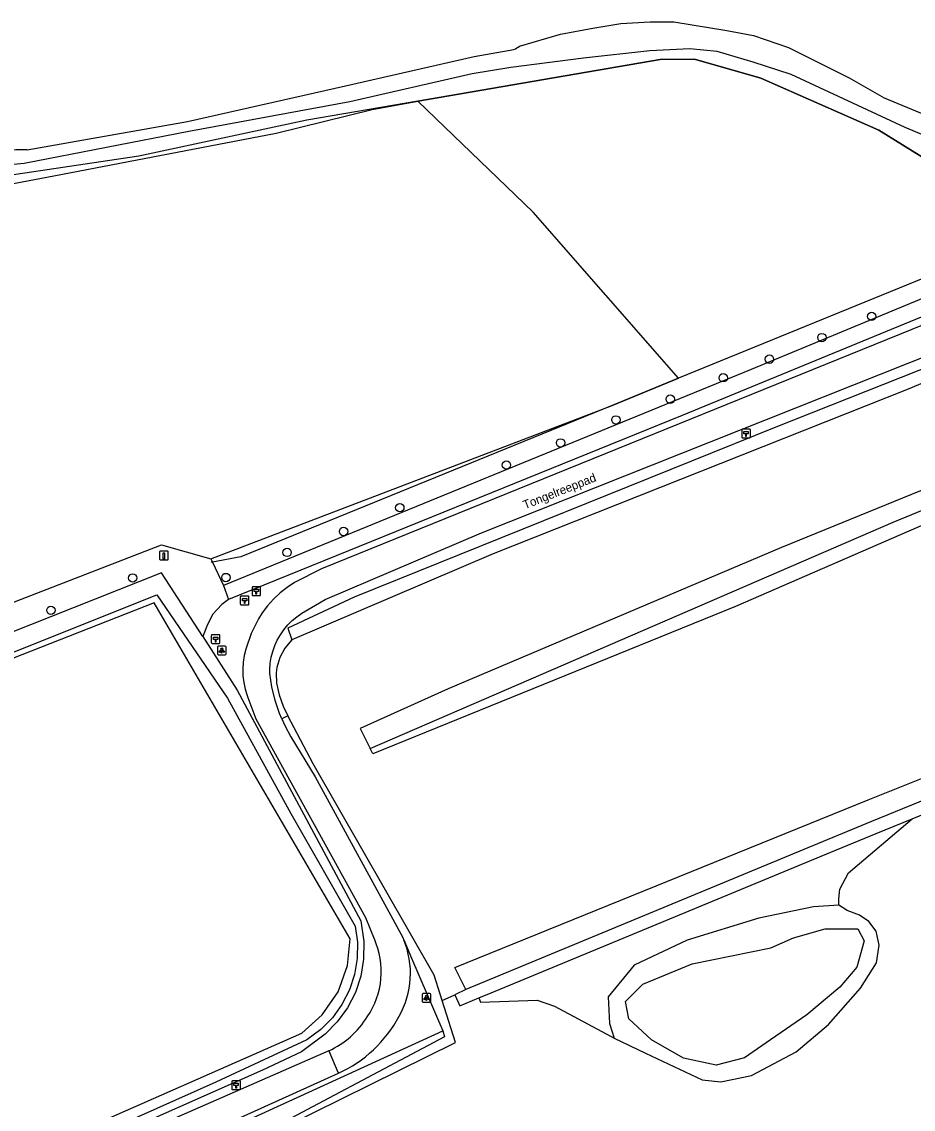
# Model space of a CAD drawing. Extents: x 160203 to 161526, y 379529 to 381797.
# Drawn here: x 161344.7 to 161448.3, y 381317.5 to 381443.9 of the extents above; entities that cross this region are included whole.
import ezdxf

# ---------------------------------------------------------------- set-up
doc = ezdxf.new("R2010")
doc.units = 0
for name, color, linetype in [('IMGEO_Boom', 7, 'Continuous'), ('IMGEO_Gemengd_bos', 7, 'Continuous'), ('IMGEO_Grasland_agrarisch', 7, 'Continuous'), ('IMGEO_Grasland_overig', 7, 'Continuous'), ('IMGEO_Hectometerpaal', 7, 'Continuous'), ('IMGEO_Hek', 7, 'Continuous'), ('IMGEO_Lichtpunt', 7, 'Continuous'), ('IMGEO_Loofbos', 7, 'Continuous'), ('IMGEO_Meer_plas_ven_vijver', 7, 'Continuous'), ('IMGEO_Openbare_ruimte_label', 7, 'Continuous'), ('IMGEO_Paal', 7, 'Continuous'), ('IMGEO_Rijbaan_lokaal_gesloten', 7, 'Continuous'), ('IMGEO_Rijbaan_lokaal_halfverhard', 7, 'Continuous'), ('IMGEO_Voetpad_onverhard', 7, 'Continuous'), ('IMGEO_Waterloop', 7, 'Continuous')]:
    doc.layers.add(name, color=color, linetype=linetype)

msp = doc.modelspace()

# ---------------------------------------------------------------- linework, layer by layer
at = {"layer": 'IMGEO_Boom'}
for centre in [(161443.45, 381409.65), (161437.67, 381407.18), (161431.57, 381404.67), (161426.21, 381402.51), (161420.05, 381400.02), (161413.74, 381397.61), (161407.31, 381394.94), (161401.01, 381392.37), (161388.62, 381387.41), (161382.09, 381384.64), (161375.52, 381382.21), (161368.42, 381379.29), (161357.58, 381379.24), (161348.08, 381375.48)]:
    msp.add_circle(centre, 0.489, dxfattribs=at)
at = {"layer": 'IMGEO_Gemengd_bos'}
for points in [[(161421.01, 381402.45), (161404.11, 381421.75), (161390.71, 381434.67)], [(161461.38, 381418.93), (161421.01, 381402.45)]]:
    msp.add_lwpolyline(points, dxfattribs=at)
at = {"layer": 'IMGEO_Grasland_agrarisch'}
for points in [[(161366.65, 381381.48), (161413.3, 381399.3), (161421.01, 381402.45)], [(161300.42, 381292.52), (161377.22, 381326.32), (161379.59, 381328.48), (161381.46, 381331.14), (161382.56, 381334.21), (161382.85, 381337.29), (161360.06, 381376.34), (161223.13, 381322.55)], [(161376.08, 381372.04), (161375.28, 381371.1), (161374.7, 381370.01), (161374.35, 381368.83), (161374.27, 381368.21), (161374.3, 381367.02), (161374.62, 381365.65), (161375.08, 381364.32), (161375.6, 381363.2)], [(161413.54, 381325.76), (161417.16, 381324.01), (161423.76, 381320.89), (161425.94, 381320.66), (161429.49, 381321.4), (161434.69, 381324.15), (161438.42, 381327.35), (161442.14, 381331.58), (161444.03, 381334.51), (161444.32, 381336.57), (161443.97, 381338.17), (161443.11, 381339.31), (161442.03, 381340.05), (161440.6, 381340.57), (161439.62, 381341.2)], [(161393.54, 381330.12), (161395.02, 381330.77)]]:
    msp.add_lwpolyline(points, dxfattribs=at)
at = {"layer": 'IMGEO_Grasland_overig'}
for points in [[(161477.98, 381397.82), (161427.64, 381375.92), (161385.47, 381358.79), (161385.17, 381359.4)], [(161375.6, 381363.2), (161374.93, 381362.86)], [(161393.54, 381330.12), (161392.6, 381333.07), (161378.56, 381357.65), (161375.6, 381363.2)], [(161439.62, 381341.2), (161439.62, 381341.94), (161439.74, 381343.08), (161440.77, 381344.97), (161448.15, 381351.25)], [(161439.62, 381341.2), (161436.69, 381341.02), (161430.33, 381339.69), (161422.02, 381337.13), (161415.85, 381334.22), (161412.82, 381330.54), (161413, 381327.46), (161413.54, 381325.76)], [(161389.08, 381337.19), (161390, 381335.06), (161393.64, 381326.61)], [(161371.98, 381313.8), (161395.1, 381325.23), (161393.54, 381330.12)], [(161397.82, 381330.42), (161397.99, 381329.92), (161404.58, 381330.15), (161406.58, 381329.47), (161413.17, 381325.94), (161413.54, 381325.76)]]:
    msp.add_lwpolyline(points, dxfattribs=at)
at = {"layer": 'IMGEO_Hectometerpaal'}
for p, q in [((161428.36, 381396.46), (161428.36, 381395.62)), ((161428.36, 381396.46), (161428.36, 381395.62)), ((161429.27, 381396.54), (161428.43, 381396.54)), ((161429.27, 381396.54), (161428.43, 381396.54)), ((161429.36, 381395.63), (161429.36, 381396.47)), ((161429.36, 381395.63), (161429.36, 381396.47)), ((161428.44, 381395.54), (161429.28, 381395.54)), ((161428.44, 381395.54), (161429.28, 381395.54)), ((161371.45, 381378.12), (161371.45, 381377.28)), ((161371.45, 381378.12), (161371.45, 381377.28)), ((161372.36, 381378.2), (161371.52, 381378.2)), ((161372.36, 381378.2), (161371.52, 381378.2)), ((161372.45, 381377.29), (161372.45, 381378.13)), ((161372.45, 381377.29), (161372.45, 381378.13)), ((161370.09, 381377.03), (161370.09, 381376.19)), ((161370.09, 381377.03), (161370.09, 381376.19)), ((161371.01, 381377.12), (161370.16, 381377.12)), ((161371.01, 381377.12), (161370.16, 381377.12)), ((161370.17, 381376.12), (161371.02, 381376.12)), ((161370.17, 381376.12), (161371.02, 381376.12)), ((161371.09, 381376.2), (161371.09, 381377.04)), ((161371.09, 381376.2), (161371.09, 381377.04)), ((161371.53, 381377.2), (161372.37, 381377.2)), ((161371.53, 381377.2), (161372.37, 381377.2)), ((161366.72, 381372.56), (161366.72, 381371.71)), ((161366.72, 381372.56), (161366.72, 381371.71)), ((161367.64, 381372.64), (161366.8, 381372.64)), ((161367.64, 381372.64), (161366.8, 381372.64)), ((161367.72, 381371.72), (161367.72, 381372.57)), ((161367.72, 381371.72), (161367.72, 381372.57)), ((161366.81, 381371.64), (161367.65, 381371.64)), ((161366.81, 381371.64), (161367.65, 381371.64)), ((161369.11, 381320.7), (161369.11, 381319.86)), ((161369.11, 381320.7), (161369.11, 381319.86)), ((161370.02, 381320.78), (161369.18, 381320.78)), ((161370.02, 381320.78), (161369.18, 381320.78)), ((161370.1, 381319.87), (161370.1, 381320.71)), ((161370.1, 381319.87), (161370.1, 381320.71)), ((161369.19, 381319.78), (161370.03, 381319.78)), ((161369.19, 381319.78), (161370.03, 381319.78))]:
    msp.add_line(p, q, dxfattribs=at)
for points in [[(161428.88, 381395.69), (161428.82, 381395.69), (161428.82, 381395.99), (161428.6, 381395.99), (161428.6, 381396.26), (161429.1, 381396.26), (161429.1, 381395.99), (161428.88, 381395.99), (161428.88, 381395.69)], [(161371.97, 381377.35), (161371.91, 381377.35), (161371.91, 381377.65), (161371.69, 381377.65), (161371.69, 381377.92), (161372.19, 381377.92), (161372.19, 381377.65), (161371.97, 381377.65), (161371.97, 381377.35)], [(161370.62, 381376.26), (161370.56, 381376.26), (161370.56, 381376.57), (161370.34, 381376.57), (161370.34, 381376.84), (161370.84, 381376.84), (161370.84, 381376.57), (161370.62, 381376.57), (161370.62, 381376.26)], [(161367.25, 381371.78), (161367.19, 381371.78), (161367.19, 381372.09), (161366.97, 381372.09), (161366.97, 381372.36), (161367.47, 381372.36), (161367.47, 381372.09), (161367.25, 381372.09), (161367.25, 381371.78)], [(161369.63, 381319.93), (161369.57, 381319.93), (161369.57, 381320.23), (161369.35, 381320.23), (161369.35, 381320.5), (161369.85, 381320.5), (161369.85, 381320.23), (161369.63, 381320.23), (161369.63, 381319.93)]]:
    msp.add_lwpolyline(points, dxfattribs=at)
for centre, start, end in [((161428.43, 381396.46), 92.4484, 184.2845), ((161428.43, 381396.46), 92.4484, 184.2845), ((161429.28, 381396.46), 2.4484, 94.2845), ((161429.28, 381396.46), 2.4484, 94.2845), ((161428.43, 381395.62), 182.4484, 274.2845), ((161428.43, 381395.62), 182.4484, 274.2845), ((161429.28, 381395.62), 272.4484, 4.2845), ((161429.28, 381395.62), 272.4484, 4.2845), ((161371.53, 381378.12), 92.4484, 184.2845), ((161371.53, 381378.12), 92.4484, 184.2845), ((161371.53, 381377.28), 182.4484, 274.2845), ((161371.53, 381377.28), 182.4484, 274.2845), ((161372.37, 381378.12), 2.4484, 94.2845), ((161372.37, 381378.12), 2.4484, 94.2845), ((161372.37, 381377.28), 272.4484, 4.2845), ((161372.37, 381377.28), 272.4484, 4.2845), ((161370.17, 381377.04), 92.4484, 184.2845), ((161370.17, 381377.04), 92.4484, 184.2845), ((161370.17, 381376.2), 182.4484, 274.2845), ((161370.17, 381376.2), 182.4484, 274.2845), ((161371.01, 381377.04), 2.4484, 94.2845), ((161371.01, 381377.04), 2.4484, 94.2845), ((161371.01, 381376.2), 272.4484, 4.2845), ((161371.01, 381376.2), 272.4484, 4.2845), ((161366.8, 381372.56), 92.4484, 184.2845), ((161366.8, 381372.56), 92.4484, 184.2845), ((161367.65, 381372.56), 2.4484, 94.2845), ((161367.65, 381372.56), 2.4484, 94.2845), ((161366.8, 381371.72), 182.4484, 274.2845), ((161366.8, 381371.72), 182.4484, 274.2845), ((161367.65, 381371.72), 272.4484, 4.2845), ((161367.65, 381371.72), 272.4484, 4.2845), ((161369.18, 381320.7), 92.4484, 184.2845), ((161369.18, 381320.7), 92.4484, 184.2845), ((161370.03, 381320.7), 2.4484, 94.2845), ((161370.03, 381320.7), 2.4484, 94.2845), ((161369.18, 381319.86), 182.4484, 274.2845), ((161369.18, 381319.86), 182.4484, 274.2845), ((161370.03, 381319.86), 272.4484, 4.2845), ((161370.03, 381319.86), 272.4484, 4.2845)]:
    msp.add_arc(centre, 0.0779, start, end, dxfattribs=at)
at = {"layer": 'IMGEO_Hek'}
for points in [[(161461.38, 381418.93), (161460.88, 381420.19), (161457.83, 381422.88), (161444.27, 381431.28), (161430.57, 381437.32), (161422.85, 381439.54), (161418.88, 381439.5), (161390.71, 381434.67)], [(161390.71, 381434.67), (161377.8, 381432.45), (161358.29, 381428.28), (161335.14, 381424.83), (161323.67, 381420.86), (161316.26, 381417.47), (161305.01, 381413.91), (161280.48, 381402.76)], [(161461.38, 381418.93), (161421.01, 381402.45)], [(161421.01, 381402.45), (161413.3, 381399.3)], [(161413.3, 381399.3), (161370.15, 381381.69), (161366.84, 381381.09)], [(161366.65, 381381.48), (161366.84, 381381.09)], [(161366.84, 381381.09), (161366.69, 381381.07)], [(161366.84, 381381.09), (161368.12, 381378.37)], [(161300.42, 381292.52), (161377.22, 381326.32), (161379.59, 381328.48), (161381.46, 381331.14), (161382.56, 381334.21), (161382.85, 381337.29), (161360.06, 381376.34), (161223.13, 381322.55)]]:
    msp.add_lwpolyline(points, dxfattribs=at)
at = {"layer": 'IMGEO_Lichtpunt'}
for p, q in [((161367.44, 381371.22), (161367.44, 381370.41)), ((161367.44, 381371.22), (161367.44, 381370.41)), ((161368.34, 381371.31), (161367.53, 381371.31)), ((161368.34, 381371.31), (161367.53, 381371.31)), ((161368.43, 381370.41), (161368.43, 381371.22)), ((161368.43, 381370.41), (161368.43, 381371.22)), ((161367.53, 381370.32), (161368.34, 381370.32)), ((161367.53, 381370.32), (161368.34, 381370.32)), ((161391.22, 381330.83), (161391.22, 381330.03)), ((161391.22, 381330.83), (161391.22, 381330.03)), ((161392.12, 381330.93), (161391.31, 381330.93)), ((161392.12, 381330.93), (161391.31, 381330.93)), ((161392.22, 381330.03), (161392.22, 381330.83)), ((161392.22, 381330.03), (161392.22, 381330.83)), ((161391.31, 381329.93), (161392.12, 381329.93)), ((161391.31, 381329.93), (161392.12, 381329.93))]:
    msp.add_line(p, q, dxfattribs=at)
for points in [[(161367.81, 381370.88), (161367.85, 381370.86), (161367.66, 381370.59), (161367.62, 381370.62), (161367.81, 381370.88)], [(161367.91, 381370.84), (161367.96, 381370.84), (161367.96, 381370.51), (161367.91, 381370.51), (161367.91, 381370.84)], [(161368.02, 381370.86), (161368.06, 381370.88), (161368.25, 381370.62), (161368.21, 381370.59), (161368.02, 381370.86)], [(161391.59, 381330.5), (161391.63, 381330.47), (161391.45, 381330.21), (161391.41, 381330.23), (161391.59, 381330.5)], [(161391.81, 381330.47), (161391.84, 381330.5), (161392.03, 381330.23), (161391.99, 381330.21), (161391.81, 381330.47)], [(161391.7, 381330.45), (161391.74, 381330.45), (161391.74, 381330.13), (161391.7, 381330.13), (161391.7, 381330.45)]]:
    msp.add_lwpolyline(points, dxfattribs=at)
for centre in [(161367.94, 381371.02), (161391.72, 381330.63)]:
    msp.add_circle(centre, 0.0994, dxfattribs=at)
for centre, start, end in [((161367.53, 381371.22), 90, 180), ((161367.53, 381371.22), 90, 180), ((161368.34, 381371.22), 0, 90), ((161368.34, 381371.22), 0, 90), ((161367.53, 381370.41), 180, 270), ((161367.53, 381370.41), 180, 270), ((161368.34, 381370.41), 270, 0), ((161368.34, 381370.41), 270, 360), ((161391.31, 381330.83), 90, 180), ((161391.31, 381330.83), 90, 180), ((161392.12, 381330.83), 0, 90), ((161392.12, 381330.83), 0, 90), ((161391.31, 381330.03), 180, 270), ((161391.31, 381330.03), 180, 270), ((161392.12, 381330.03), 270, 0), ((161392.12, 381330.03), 270, 360)]:
    msp.add_arc(centre, 0.0946, start, end, dxfattribs=at)
at = {"layer": 'IMGEO_Loofbos'}
for points in [[(161448.15, 381351.25), (161475.37, 381362.37), (161489.26, 381368.04), (161488.64, 381369.4)], [(161397.82, 381330.42), (161399.23, 381331.01), (161404.18, 381333.06), (161438.72, 381347.37), (161443.96, 381349.54), (161448.15, 381351.25)], [(161396.31, 381331.42), (161395.02, 381330.77)], [(161395.02, 381330.77), (161395.6, 381329.51), (161397.82, 381330.42)]]:
    msp.add_lwpolyline(points, dxfattribs=at)
at = {"layer": 'IMGEO_Meer_plas_ven_vijver'}
msp.add_lwpolyline([(161438.04, 381338.47), (161441.85, 381338.47), (161442.59, 381337.05), (161441.72, 381334.01), (161439.74, 381331.67), (161435.93, 381328.45), (161431.7, 381325.56), (161428.66, 381323.48), (161425.4, 381322.61), (161421.59, 381323.44), (161417.87, 381325.56), (161415.25, 381327.99), (161414.83, 381330.02), (161416.86, 381332.04), (161422.6, 381334.38), (161431.72, 381336.24), (161434.36, 381337.42), (161438.04, 381338.47)], dxfattribs=at)
at = {"layer": 'IMGEO_Paal'}
for p, q in [((161361.63, 381382.35), (161360.78, 381382.35)), ((161361.63, 381382.35), (161360.78, 381382.35)), ((161361.71, 381381.44), (161361.71, 381382.28)), ((161361.71, 381381.44), (161361.71, 381382.28)), ((161360.71, 381382.27), (161360.71, 381381.43)), ((161360.71, 381382.27), (161360.71, 381381.43)), ((161360.79, 381381.35), (161361.64, 381381.35)), ((161360.79, 381381.35), (161361.64, 381381.35))]:
    msp.add_line(p, q, dxfattribs=at)
msp.add_lwpolyline([(161361.13, 381382.17), (161361.29, 381382.17), (161361.29, 381381.43), (161361.13, 381381.43), (161361.13, 381382.17)], dxfattribs=at)
for centre, start, end in [((161360.79, 381382.28), 92.4484, 184.2845), ((161360.79, 381382.28), 92.4484, 184.2845), ((161361.63, 381382.28), 2.4484, 94.2845), ((161361.63, 381382.28), 2.4484, 94.2845), ((161360.79, 381381.43), 182.4484, 274.2845), ((161360.79, 381381.43), 182.4484, 274.2845), ((161361.63, 381381.43), 272.4484, 4.2845), ((161361.63, 381381.43), 272.4484, 4.2845)]:
    msp.add_arc(centre, 0.0779, start, end, dxfattribs=at)
at = {"layer": 'IMGEO_Rijbaan_lokaal_gesloten'}
for points in [[(161469.38, 381416.15), (161468.35, 381416.31), (161468.18, 381416.24), (161379.51, 381380.32), (161376.4, 381378.7), (161375.53, 381378.14), (161374.71, 381377.5), (161373.95, 381376.79), (161373.26, 381376.02), (161372.64, 381375.18), (161372.21, 381374.5), (161371.35, 381372.78), (161370.73, 381370.97), (161370.54, 381370.21), (161370.42, 381369.44), (161370.37, 381368.65), (161370.39, 381367.87), (161370.49, 381367.09), (161370.65, 381366.33), (161370.88, 381365.58), (161370.96, 381365.35), (161371.9, 381362.86), (161384.63, 381339.79), (161385.66, 381337.28)], [(161374.93, 381362.86), (161374.65, 381363.49), (161374.14, 381365.01), (161373.76, 381366.57), (161373.53, 381368.15), (161373.52, 381368.6), (161373.57, 381369.32), (161373.69, 381370.02), (161373.86, 381370.71), (161374.1, 381371.38), (161374.39, 381372.03), (161374.74, 381372.65), (161375.15, 381373.23), (161375.6, 381373.78), (161376.11, 381374.28), (161376.65, 381374.74), (161377.24, 381375.15), (161379.93, 381376.75), (161398.12, 381384.47), (161467.77, 381412.19), (161469.08, 381412.98), (161470.21, 381414.22), (161470.56, 381414.35)], [(161374.93, 381362.86), (161375.3, 381362.02), (161375.97, 381360.78), (161378.77, 381356.14), (161388.96, 381337.45), (161389.02, 381337.32), (161389.08, 381337.19)], [(161380.36, 381324.29), (161300.01, 381289.1), (161268.1, 381275.47), (161255.77, 381270.11)], [(161380.36, 381324.29), (161381.43, 381321.81), (161381.5, 381321.67)], [(161108.29, 381192.8), (161114.38, 381197.57), (161123.38, 381204.59), (161125.79, 381205.94), (161175.21, 381228.65), (161209.02, 381245.57), (161218.78, 381250), (161257.16, 381267.43), (161261.42, 381269.36), (161301.19, 381286.35), (161354.19, 381309.33), (161381.5, 381321.67)]]:
    msp.add_lwpolyline(points, dxfattribs=at)
for centre, radius, start, end in [((161377.16, 381333.49), 9.31, 325.6381, 24.0278), ((161379.8, 381333.29), 10.06, 330.247, 22.7745), ((161376.22, 381333.51), 10.11, 294.177, 328.5272), ((161375.34, 381335.25), 14.91, 294.3759, 332.2212)]:
    msp.add_arc(centre, radius, start, end, dxfattribs=at)
at = {"layer": 'IMGEO_Rijbaan_lokaal_halfverhard'}
for points in [[(161267.77, 381346.99), (161360.92, 381383.1), (161366.65, 381381.48)], [(161366.65, 381381.48), (161366.84, 381381.09), (161368.12, 381378.37)], [(161365.72, 381372.42), (161360.95, 381379.85), (161271.8, 381344.48)], [(161368.12, 381378.37), (161368.71, 381376.75)], [(161368.71, 381376.75), (161367.93, 381376.17), (161366.87, 381374.98), (161366.2, 381373.65), (161365.72, 381372.42)]]:
    msp.add_lwpolyline(points, dxfattribs=at)
at = {"layer": 'IMGEO_Voetpad_onverhard'}
for points in [[(161458.71, 381424.79), (161457.27, 381425.64), (161457.1, 381427.27), (161452.08, 381429.64), (161447.34, 381431.6), (161434.1, 381437.78), (161429.69, 381439.19), (161425.48, 381440.42), (161422.31, 381440.76), (161417.68, 381440.53), (161409.95, 381439.65), (161401.52, 381438.59), (161397.03, 381437.84), (161382.83, 381434.58), (161364.12, 381431.14), (161344.99, 381427.42)], [(161390.71, 381434.67), (161418.88, 381439.5), (161422.85, 381439.54), (161430.57, 381437.32), (161444.27, 381431.28), (161457.83, 381422.88), (161460.88, 381420.19), (161461.38, 381418.93)], [(161254.89, 381391.93), (161272.35, 381398.48), (161280.83, 381401.91), (161288.52, 381405.02), (161297.01, 381411.1), (161298.02, 381411.7), (161299.32, 381412.21), (161321.57, 381419.76), (161328.77, 381422.27), (161348.41, 381425.98), (161374.24, 381430.94), (161385.42, 381433.68), (161390.71, 381434.67)]]:
    msp.add_lwpolyline(points, dxfattribs=at)
msp.add_arc((161351.43, 381336.74), 90.9, 94.0642, 106.6748, dxfattribs=at)
at = {"layer": 'IMGEO_Waterloop'}
for points in [[(161402.52, 381441.05), (161407.31, 381442.46), (161411.06, 381443.15), (161414.32, 381443.69), (161417.7, 381443.89), (161420.45, 381443.88), (161426.64, 381442.88), (161429.72, 381442.29), (161433.79, 381440.9), (161440.85, 381437.36), (161444.89, 381435.03), (161449.68, 381433.06), (161455.17, 381430.69), (161458.15, 381428.97), (161459.47, 381428.31), (161459.99, 381427.11), (161459.81, 381426.32), (161460.08, 381425.72), (161466.35, 381421.22), (161466.64, 381420.96), (161469.59, 381416.27)], [(161345.31, 381429), (161363.94, 381432.29), (161382.3, 381436.45), (161397.27, 381439.85), (161401.89, 381440.65)], [(161462.15, 381417.02), (161429.46, 381403.48), (161368.12, 381378.37)], [(161464.09, 381415.66), (161421.45, 381398.12), (161368.71, 381376.75)], [(161471.26, 381412.2), (161471.21, 381411.96), (161468.66, 381411.19), (161467.8, 381410.83), (161432.33, 381396.76), (161383.33, 381377), (161375.63, 381373.42), (161376.08, 381372.04)], [(161472.76, 381410.64), (161472.16, 381410.46), (161469.33, 381409.61), (161468.48, 381409.25), (161468.22, 381409.17), (161460.82, 381406.69), (161453.41, 381403.58), (161447.71, 381401.19), (161399.46, 381382.06), (161376.08, 381372.04)], [(161476.9, 381400.38), (161467.16, 381396.73), (161432.99, 381382.78), (161394.26, 381366.35), (161384, 381361.75), (161385.17, 381359.4)], [(161385.17, 381359.4), (161445.95, 381385.74), (161474.15, 381397.31), (161476.06, 381397.87), (161477.86, 381398.12)], [(161222.84, 381323.27), (161236, 381328.12), (161256.58, 381336.04), (161274.27, 381343.43), (161317.03, 381359.97), (161360.4, 381377.29), (161368.59, 381365.27), (161375.96, 381351.87), (161383.45, 381338.75), (161383.7, 381336.92), (161383.67, 381335.02), (161383.36, 381333.15), (161382.76, 381331.35), (161381.9, 381329.65), (161380.79, 381328.11), (161379.45, 381326.76), (161377.81, 381325.55), (161367.25, 381320.64), (161353.54, 381314.51), (161316.1, 381298.26), (161316.62, 381297.13)], [(161365.72, 381372.42), (161369.71, 381366.2), (161384.11, 381339.39), (161384.45, 381336.97), (161384.42, 381334.95), (161384.09, 381332.97), (161383.46, 381331.05), (161382.54, 381329.26), (161381.36, 381327.63), (161379.94, 381326.2), (161377.2, 381324.16), (161372.67, 381322.04), (161352.58, 381313.11), (161328.84, 381302.29), (161316.62, 381297.13)], [(161396.31, 381331.42), (161395.03, 381333.97), (161443.05, 381353.46), (161473.83, 381365.79), (161487.76, 381371.36), (161489, 381371.86)], [(161488.64, 381369.4), (161474.74, 381363.73), (161443.43, 381350.95), (161439.4, 381349.28), (161396.31, 381331.42)], [(161195.51, 381236.36), (161194.88, 381237.74), (161206.8, 381242.94), (161222.45, 381250), (161231.6, 381254.13), (161253.42, 381264.34), (161286.37, 381278.95), (161342.74, 381303.34), (161367.3, 381314.56), (161367.99, 381314.88), (161393.64, 381326.61)], [(161393.64, 381326.61), (161393.83, 381325.91), (161371.48, 381314.03), (161371.6, 381313.62)]]:
    msp.add_lwpolyline(points, dxfattribs=at)
for centre, radius, start, end in [((161399.21, 381445.54), 5.57, 298.7391, 306.3692), ((161344.83, 381360.52), 68.48, 89.5979, 106.9955)]:
    msp.add_arc(centre, radius, start, end, dxfattribs=at)

# ---------------------------------------------------------------- texts
at = {"layer": 'IMGEO_Openbare_ruimte_label'}
msp.add_text('Tongelreeppad', height=1, rotation=21.5354, dxfattribs=at).set_placement((161403.17, 381387.22))

doc.saveas('drawing.dxf')
